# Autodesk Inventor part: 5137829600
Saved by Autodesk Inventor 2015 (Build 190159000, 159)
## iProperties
Created: 2020-07
Part Number: 5137829600
Checked By: TraceParts S.A.
Material: Generic
Catalog Web Link: www.traceparts.com
Document SubType Name: Modeling
Designer: TraceParts
Density: 1 g/cm^3
Appearance: Default
Company: TraceParts S.A.
Author: TraceParts
REFERENCE: 5137829600
DESIGN: CVAB-1400/250 N ECOWATT 0,20KW (230V 50/60HZ) N8 - 5137829600
SUPPLIER: Soler & Palau
TraceParts.PartNumber: 10-20122018-119636
TraceParts.PartTitle: CVAB/T-N_ECO
TraceParts.InstanceId: 10-20122018-119636CTKQ1W4UUG5L50DTJSGY47KWT
TraceParts.PartStatus: Published
TraceParts.PartVersion: 1.0.2
TRACEPARTS: TRACEPARTS
TraceParts.PartLanguage: en
TraceParts.ClassPath: SOLER_PALAU:10-20122018-119636
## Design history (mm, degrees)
feature "5137829600"
body "Solid1"
